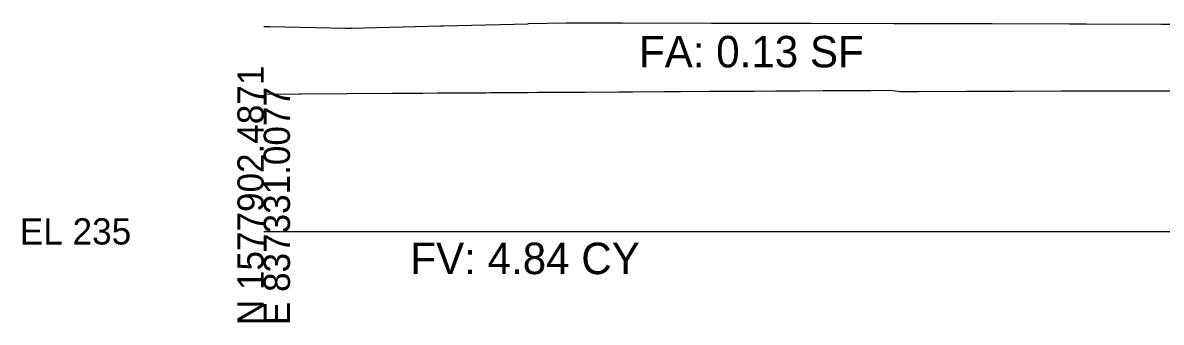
# Model space of a CAD drawing. Extents: x -26 to 303, y -16 to 6048.
# Drawn here: x -25.7 to 95.7, y 3990.3 to 4022.3 of the extents above; entities that cross this region are included whole.
import ezdxf

# ---------------------------------------------------------------- set-up
doc = ezdxf.new("R2010")
doc.units = 0
for name, color, linetype in [('Draft_XS_Grid', 7, 'Continuous'), ('DTM_X_GROUND', 7, 'Continuous'), ('XS_CELL', 7, 'Continuous'), ('XS_P_GROUND', 7, 'Continuous'), ('XS_SHEET_EW_TX_AREA', 7, 'Continuous'), ('XS_SHEET_EW_TX_VOLUME', 7, 'Continuous')]:
    doc.layers.add(name, color=color, linetype=linetype)

msp = doc.modelspace()

# ---------------------------------------------------------------- linework, layer by layer
at = {"layer": 'DTM_X_GROUND'}
msp.add_lwpolyline([(0, 4021.86), (0.65, 4021.87), (8.74, 4021.67), (9.37, 4021.69), (18.84, 4021.93), (19.19, 4021.94), (28.17, 4022.16), (28.24, 4022.17), (32.27, 4022.26), (38.04, 4022.25), (38.23, 4022.25), (47.77, 4022.23), (48.29, 4022.23), (57.5, 4022.22), (58.35, 4022.22), (67.23, 4022.2), (68.4, 4022.2), (76.32, 4022.19), (77.69, 4022.19), (85.95, 4022.15), (87.74, 4022.15), (95.69, 4022.11), (97.8, 4022.11)], dxfattribs=at)
msp.add_lwpolyline([(0, 4021.86), (0.65, 4021.87), (8.74, 4021.67), (9.37, 4021.69), (18.84, 4021.93), (19.19, 4021.94), (28.17, 4022.16), (28.24, 4022.17), (32.27, 4022.26), (38.04, 4022.25), (38.23, 4022.25), (47.77, 4022.23), (48.29, 4022.23), (57.5, 4022.22), (58.35, 4022.22), (67.23, 4022.2), (68.4, 4022.2), (76.32, 4022.19), (77.69, 4022.19), (85.95, 4022.15), (87.74, 4022.15), (95.69, 4022.11), (97.8, 4022.11)], dxfattribs=at)
at = {"layer": 'XS_CELL'}
msp.add_line((0, 4000), (150, 4000), dxfattribs=at)
at = {"layer": 'XS_P_GROUND'}
msp.add_lwpolyline([(0, 4014.66), (3.81, 4014.68), (4.02, 4014.69), (8.85, 4014.72), (8.89, 4014.72), (13.69, 4014.74), (13.97, 4014.75), (16.96, 4014.76), (18.52, 4014.77), (19.05, 4014.78), (23.36, 4014.8), (23.7, 4014.8), (24.13, 4014.81), (28.19, 4014.83), (29.21, 4014.84), (33.02, 4014.86), (34.29, 4014.87), (37.86, 4014.89), (39.37, 4014.9), (42.69, 4014.92), (44.45, 4014.93), (47.52, 4014.95), (49.53, 4014.96), (49.76, 4014.96), (52.35, 4014.98), (54.6, 4014.99), (57.18, 4015.01), (59.68, 4015.02), (60.92, 4015.03), (62.02, 4015.04), (64.76, 4015.05), (66.85, 4015.07), (67.92, 4014.91), (68.94, 4014.92), (69.84, 4014.92), (74.91, 4014.95), (77.36, 4014.97), (79.99, 4014.98), (85.06, 4014.99), (90.14, 4014.99), (91.42, 4014.99), (95.21, 4015), (99.07, 4015)], dxfattribs=at)

# ---------------------------------------------------------------- texts
at = {"layer": 'Draft_XS_Grid'}
msp.add_text('-', height=0.0001, dxfattribs=at).set_placement((0, 4000))
at = {"layer": 'XS_CELL'}
for s, p in [('N 1577902.4871', (0, 3990)), ('E 837331.0077', (2.8, 3990))]:
    msp.add_text(s, height=2.8, rotation=90, dxfattribs=at).set_placement(p)
msp.add_text('EL 235', height=2.8, dxfattribs=at).set_placement((-26, 3998.6))
at = {"layer": 'XS_SHEET_EW_TX_AREA'}
msp.add_text('FA: 0.13 SF', height=3.36, dxfattribs=at).set_placement((40.02, 4017.5))
at = {"layer": 'XS_SHEET_EW_TX_VOLUME'}
msp.add_text('FV: 4.84 CY', height=3.36, dxfattribs=at).set_placement((15.64, 3995.44))

doc.saveas('drawing.dxf')
